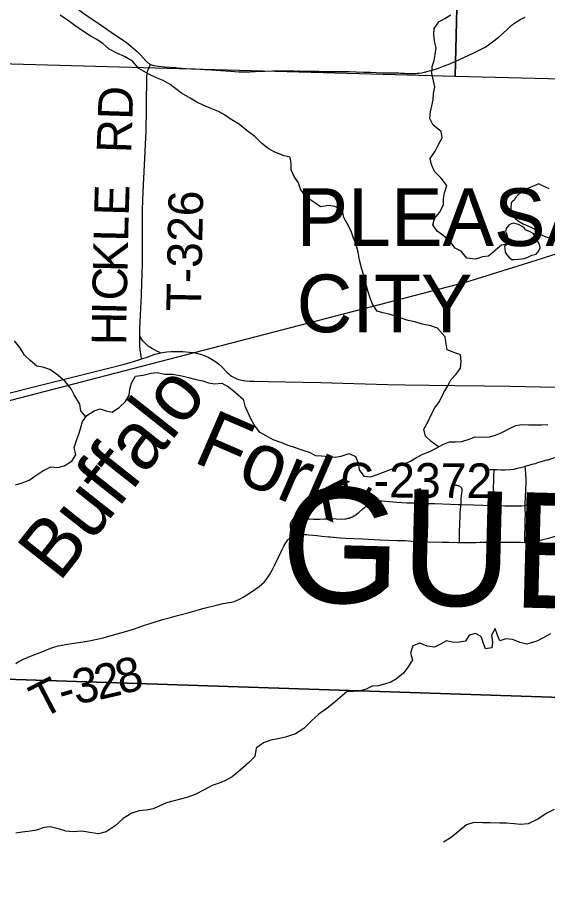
# Model space of a CAD drawing. Extents: x 0 to 34, y 0 to 22.
# Drawn here: x 5.129 to 5.999, y 19.787 to 21.203 of the extents above; entities that cross this region are included whole.
import ezdxf

# ---------------------------------------------------------------- set-up
doc = ezdxf.new("R2010")
doc.units = 0
for name, color, linetype in [('GM_X_Corporation', 7, 'Continuous'), ('GM_X_Corporation_Text', 7, 'Continuous'), ('GM_X_County_Road_Text', 7, 'Continuous'), ('GM_X_County_Text', 7, 'Continuous'), ('GM_X_Minor_Lake', 7, 'Continuous'), ('GM_X_Minor_River', 7, 'Continuous'), ('GM_X_Minor_River_Text', 7, 'Continuous'), ('GM_X_Rail_Line', 7, 'Continuous'), ('GM_X_State_Route', 7, 'Continuous'), ('GM_X_Township_Road', 7, 'Continuous'), ('GM_X_Township_Road_Text', 7, 'Continuous')]:
    doc.layers.add(name, color=color, linetype=linetype)

msp = doc.modelspace()

# ---------------------------------------------------------------- linework, layer by layer
at = {"layer": 'GM_X_Corporation'}
for points in [[(4.7823, 18.128), (4.7905, 18.3604), (4.8074, 19.5455), (4.8169, 20.042), (4.8194, 20.1261), (5.11, 20.116), (6.0551, 20.0845), (6.4901, 20.0752), (6.7204, 20.0659), (7.3691, 20.0515), (7.3901, 20.051), (7.814, 20.0425), (8.4311, 20.028), (8.4311, 21.3734), (1.6311, 21.3734)], [(4.0508, 18.1454), (4.7823, 18.128), (4.7905, 18.3604), (4.8074, 19.5455), (4.8169, 20.042), (4.8194, 20.1261), (5.11, 20.116), (6.0551, 20.0845), (6.4901, 20.0752), (6.7204, 20.0659), (7.3691, 20.0515), (7.3901, 20.051), (7.814, 20.0425), (8.4311, 20.028), (8.4311, 21.3734), (2.7987, 21.3734)], [(8.4311, 14.5734), (8.4311, 20.028), (7.814, 20.0425), (7.3901, 20.051), (7.3691, 20.0515), (6.7204, 20.0659), (6.4901, 20.0752), (6.0551, 20.0845), (5.11, 20.116), (4.8194, 20.1261), (4.8169, 20.042), (4.8074, 19.5455), (4.7905, 18.3604), (4.7823, 18.128)], [(8.4311, 16.0029), (8.4311, 20.028), (7.814, 20.0425), (7.3901, 20.051), (7.3691, 20.0515), (6.7204, 20.0659), (6.4901, 20.0752), (6.0551, 20.0845), (5.11, 20.116), (4.8194, 20.1261), (4.8169, 20.042), (4.8074, 19.5455), (4.7905, 18.3604), (4.7823, 18.128)]]:
    msp.add_lwpolyline(points, dxfattribs=at)
for points in [[(5.8536, 21.3734), (4.8467, 21.3734), (4.8451, 21.1681), (4.8435, 21.134), (5.8473, 21.1062)], [(6.8607, 21.3734), (5.8536, 21.3734), (5.8473, 21.1062), (6.8544, 21.0806)]]:
    msp.add_lwpolyline(points, close=True, dxfattribs=at)
at = {"layer": 'GM_X_Minor_Lake'}
for points in [[(6.0013, 20.9209), (5.9945, 20.9242), (5.9895, 20.9265), (5.9846, 20.9291), (5.9767, 20.9259), (5.9661, 20.9213), (5.9676, 20.9213), (5.9605, 20.9171), (5.9533, 20.9132), (5.9507, 20.9113), (5.9459, 20.9059), (5.9447, 20.9029), (5.941, 20.8998), (5.9391, 20.8979), (5.9384, 20.8892), (5.9392, 20.885), (5.9393, 20.8824), (5.9408, 20.8778), (5.9465, 20.8718), (5.9522, 20.8673), (5.9591, 20.8636), (5.9667, 20.8603), (5.9712, 20.8581), (5.9807, 20.8529), (5.9891, 20.8457), (5.9959, 20.8424), (6.0031, 20.8406)], [(5.9858, 20.8294), (5.9808, 20.8381), (5.9797, 20.8419), (5.9751, 20.8479), (5.9694, 20.8508), (5.9629, 20.8538), (5.9606, 20.8568), (5.9572, 20.859), (5.9511, 20.8624), (5.9432, 20.8646), (5.939, 20.8634), (5.9353, 20.8611), (5.9308, 20.8557), (5.9304, 20.8527), (5.9301, 20.8512), (5.9309, 20.8489), (5.9324, 20.844), (5.9328, 20.8414), (5.9333, 20.8304)], [(5.9333, 20.8304), (5.928, 20.8269), (5.9288, 20.8224), (5.9296, 20.8171), (5.9319, 20.8129), (5.9361, 20.8081), (5.9403, 20.8051), (5.9441, 20.8051), (5.952, 20.8056), (5.9607, 20.8068), (5.9652, 20.8084), (5.9731, 20.8119), (5.9803, 20.8138), (5.9833, 20.8173), (5.9844, 20.8192), (5.9866, 20.8241), (5.9858, 20.8294)]]:
    msp.add_lwpolyline(points, dxfattribs=at)
at = {"layer": 'GM_X_Minor_River'}
for points in [[(5.82, 20.4972), (5.808, 20.5059), (5.7984, 20.5149), (5.7961, 20.5266), (5.8028, 20.5388), (5.808, 20.5498), (5.8139, 20.5612), (5.8218, 20.5719), (5.8288, 20.5864), (5.8351, 20.5975), (5.8403, 20.6074), (5.849, 20.6169), (5.8561, 20.6265), (5.8571, 20.6379), (5.8562, 20.6485), (5.8441, 20.6529), (5.8342, 20.6566), (5.8323, 20.6664), (5.831, 20.6781), (5.8181, 20.692), (5.8074, 20.6961), (5.7931, 20.6986), (5.7813, 20.7026), (5.7703, 20.7048), (5.7605, 20.7081), (5.751, 20.7114), (5.7392, 20.7154), (5.7286, 20.7172), (5.7192, 20.7201), (5.7115, 20.7314), (5.7076, 20.7416), (5.7041, 20.7533), (5.7002, 20.7677), (5.6975, 20.7786), (5.694, 20.7892), (5.6901, 20.8039), (5.6884, 20.8168), (5.6849, 20.8293), (5.6807, 20.8398), (5.6768, 20.8515), (5.6699, 20.864), (5.6649, 20.8738), (5.6625, 20.8851), (5.65, 20.8918), (5.6398, 20.8936), (5.6266, 20.8915), (5.6171, 20.8979), (5.6022, 20.908), (5.5938, 20.9204), (5.5903, 20.9306), (5.583, 20.9411), (5.5784, 20.952), (5.5783, 20.963), (5.5767, 20.9729), (5.5669, 20.9754), (5.5513, 20.9813), (5.5403, 20.9872), (5.5304, 20.9955), (5.5189, 21.0071), (5.506, 21.0161), (5.4935, 21.0265), (5.4782, 21.0362), (5.4687, 21.0426), (5.4589, 21.0481), (5.4456, 21.0537), (5.435, 21.0577), (5.4236, 21.0633), (5.4126, 21.07), (5.3985, 21.0782), (5.3795, 21.0924), (5.3685, 21.0991), (5.3571, 21.1035), (5.3449, 21.1091), (5.3282, 21.1188), (5.3179, 21.1308), (5.305, 21.1382), (5.2921, 21.1438), (5.2795, 21.1504), (5.2693, 21.1598), (5.2586, 21.1665), (5.2484, 21.1721), (5.2358, 21.1803), (5.2236, 21.1893), (5.213, 21.1967), (5.1993, 21.206)], [(5.9333, 20.8304), (5.9235, 20.8284), (5.9133, 20.8203), (5.9021, 20.8107), (5.8919, 20.8091), (5.8806, 20.8056), (5.8666, 20.8073), (5.857, 20.8186), (5.8475, 20.8238), (5.8387, 20.8351), (5.8273, 20.8448), (5.8178, 20.8515), (5.8109, 20.862), (5.8135, 20.8723), (5.8217, 20.8822), (5.828, 20.8948), (5.8283, 20.9047), (5.8297, 20.9145), (5.8334, 20.9263), (5.8242, 20.9383), (5.8132, 20.9492), (5.8085, 20.9609), (5.8062, 20.9707), (5.8144, 20.983), (5.8196, 20.9929), (5.8259, 21.0047), (5.8243, 21.0153), (5.8114, 21.0257), (5.806, 21.0363), (5.8066, 21.0473), (5.8088, 21.0575), (5.811, 21.067), (5.8117, 21.0776), (5.8142, 21.0883), (5.8115, 21.0981), (5.8091, 21.1106), (5.8098, 21.1216), (5.8131, 21.1315), (5.8145, 21.1413), (5.8159, 21.1523), (5.8136, 21.1637), (5.8123, 21.175), (5.813, 21.1845), (5.8205, 21.1952), (5.8302, 21.2006), (5.84, 21.2068)], [(5.2414, 20.5468), (5.233, 20.5566), (5.2317, 20.5676), (5.2225, 20.5826), (5.2175, 20.5924), (5.2076, 20.6048), (5.1954, 20.6153), (5.1821, 20.6246), (5.1707, 20.6283), (5.1609, 20.6301), (5.1502, 20.6391), (5.1407, 20.6481), (5.1334, 20.6605), (5.1242, 20.6714)], [(5.1259, 20.435), (5.1368, 20.4385), (5.1485, 20.4424), (5.1594, 20.4501), (5.1711, 20.4582), (5.1842, 20.4644), (5.1956, 20.4637), (5.2058, 20.4661), (5.2182, 20.4738), (5.2249, 20.4845), (5.2225, 20.4962), (5.2269, 20.5095), (5.2303, 20.5198), (5.2332, 20.5293), (5.2358, 20.5392), (5.2429, 20.5487), (5.2549, 20.5564), (5.2651, 20.5596), (5.2749, 20.5563), (5.2848, 20.5545), (5.2964, 20.5626), (5.3065, 20.5718), (5.3125, 20.5821), (5.3135, 20.5919), (5.3161, 20.6022), (5.3228, 20.6132), (5.3353, 20.6153), (5.3485, 20.6184), (5.3583, 20.6193), (5.3708, 20.6168), (5.3836, 20.6165), (5.3988, 20.6137), (5.4101, 20.6115), (5.4226, 20.6079), (5.4332, 20.6057), (5.4427, 20.6024), (5.4529, 20.601), (5.4647, 20.6019), (5.4757, 20.5959), (5.4871, 20.5866), (5.4993, 20.5757), (5.5024, 20.5648), (5.507, 20.5538), (5.5113, 20.544), (5.5186, 20.5316), (5.5258, 20.5218), (5.5365, 20.5162), (5.5482, 20.5096), (5.5623, 20.5044), (5.5729, 20.5), (5.585, 20.4963), (5.5972, 20.4919), (5.6078, 20.4886), (5.6184, 20.4834), (5.6282, 20.4824), (5.64, 20.4817), (5.6502, 20.4807), (5.6604, 20.4823), (5.6732, 20.4862), (5.6838, 20.4814), (5.6884, 20.4713), (5.6897, 20.4595), (5.6977, 20.449)], [(5.6977, 20.449), (5.7083, 20.448), (5.7185, 20.4515), (5.7343, 20.4577), (5.7513, 20.464), (5.7626, 20.469), (5.7739, 20.4737), (5.7836, 20.4798), (5.7942, 20.4853), (5.8055, 20.4895), (5.8175, 20.4957), (5.8273, 20.5015), (5.8378, 20.5054), (5.8477, 20.5055), (5.8582, 20.5064), (5.8703, 20.5099), (5.8801, 20.5138), (5.8922, 20.5132), (5.9039, 20.5137), (5.9137, 20.5165), (5.9239, 20.5207), (5.9356, 20.5269), (5.9468, 20.5323), (5.9567, 20.534), (5.9676, 20.5333), (5.9888, 20.5335), (5.9994, 20.534)], [(6.0039, 20.1904), (5.993, 20.1843), (5.9813, 20.1781), (5.9651, 20.1734), (5.9537, 20.1763), (5.9416, 20.1811), (5.9306, 20.1821), (5.9204, 20.1786), (5.9166, 20.1884), (5.9127, 20.1993), (5.9071, 20.1883), (5.9084, 20.1769), (5.9077, 20.1671), (5.8971, 20.1655), (5.8932, 20.1764), (5.8901, 20.1862), (5.8806, 20.1907), (5.8705, 20.1879), (5.8645, 20.1784), (5.8543, 20.1767), (5.8445, 20.1763), (5.8331, 20.1788), (5.8233, 20.1734), (5.8136, 20.1684), (5.8011, 20.1701), (5.7893, 20.1749), (5.778, 20.1706), (5.7739, 20.1588), (5.7771, 20.1479), (5.7704, 20.1361), (5.7625, 20.1258), (5.7513, 20.1165), (5.7415, 20.1108), (5.7313, 20.1076), (5.7211, 20.1052), (5.7109, 20.1047), (5.7011, 20.0997), (5.6891, 20.0963), (5.6804, 20.0958), (5.6704, 20.0955)], [(5.6704, 20.0955), (5.6508, 20.0791), (5.6368, 20.0678), (5.6235, 20.0583), (5.6118, 20.0473), (5.5993, 20.0348), (5.5856, 20.0261), (5.569, 20.0208), (5.5565, 20.0182), (5.5448, 20.0156), (5.5327, 20.0114), (5.5209, 20.0027), (5.5186, 19.9891), (5.508, 19.9785), (5.4948, 19.9667), (5.4815, 19.9558), (5.4686, 19.9482), (5.4584, 19.9444), (5.4486, 19.9414), (5.4353, 19.9342), (5.421, 19.9266), (5.4073, 19.9217), (5.3967, 19.9187), (5.3839, 19.9157), (5.374, 19.9131), (5.3627, 19.9081), (5.3517, 19.9032), (5.3407, 19.901), (5.329, 19.8995), (5.3169, 19.8961), (5.3025, 19.8874), (5.2893, 19.8749), (5.2749, 19.865), (5.262, 19.862), (5.2477, 19.8643), (5.2348, 19.8666), (5.2204, 19.8655), (5.2087, 19.8663), (5.1981, 19.8697), (5.183, 19.8735), (5.1732, 19.8724), (5.1603, 19.8678), (5.1505, 19.8663), (5.1369, 19.8648), (5.1263, 19.8633)], [(6.0097, 19.9017), (5.9968, 19.8952), (5.9828, 19.8861), (5.9673, 19.8782), (5.9544, 19.8775), (5.9442, 19.8782), (5.9317, 19.8794), (5.9208, 19.8794), (5.9045, 19.8802), (5.892, 19.8802), (5.8777, 19.8806), (5.8659, 19.8768), (5.8531, 19.8666), (5.8406, 19.856), (5.8281, 19.8481)]]:
    msp.add_lwpolyline(points, dxfattribs=at)
at = {"layer": 'GM_X_Rail_Line'}
msp.add_lwpolyline([(6.5148, 20.9732), (5.9587, 20.7967), (5.8659, 20.7679), (5.0311, 20.5511), (4.5849, 20.4354), (4.3494, 20.3746), (4.3114, 20.365), (4.2729, 20.3524), (4.2311, 20.3354), (4.2068, 20.3213), (4.1788, 20.304), (4.0429, 20.1945)], dxfattribs=at)
at = {"layer": 'GM_X_State_Route'}
msp.add_lwpolyline([(5.1172, 20.5861), (5.1539, 20.5955), (5.1998, 20.6068), (5.2239, 20.6128), (5.248, 20.619), (5.2721, 20.6251), (5.3004, 20.6322), (5.3177, 20.637), (5.3314, 20.6413), (5.3328, 20.6417), (5.3402, 20.6442), (5.3549, 20.6493), (5.3637, 20.6517), (5.3707, 20.653), (5.3745, 20.6534), (5.3813, 20.6539), (5.3901, 20.654), (5.4007, 20.6537), (5.4108, 20.6531), (5.4187, 20.6522), (5.4249, 20.6509), (5.4297, 20.6495), (5.4356, 20.6474), (5.4431, 20.644), (5.4486, 20.641), (5.4539, 20.6376), (5.4589, 20.6338), (5.4639, 20.6291), (5.4725, 20.6201), (5.4766, 20.6165), (5.4806, 20.6136), (5.4847, 20.6111), (5.4892, 20.609), (5.492, 20.608), (5.4973, 20.6066), (5.504, 20.6057), (5.5101, 20.6053), (5.5176, 20.605), (5.5406, 20.6046), (5.5691, 20.6041), (5.6269, 20.6032), (5.663, 20.6021), (5.7362, 20.6), (5.7648, 20.5994), (5.804, 20.5988), (5.8468, 20.598), (5.8953, 20.5974), (5.9375, 20.597), (6.0121, 20.5956)], dxfattribs=at)
at = {"layer": 'GM_X_Township_Road'}
for points in [[(5.1288, 21.2967), (5.1376, 21.2889), (5.1458, 21.2822), (5.1599, 21.271), (5.1798, 21.2551), (5.1932, 21.244), (5.2053, 21.2343), (5.2254, 21.2187), (5.2315, 21.214), (5.2382, 21.209), (5.2534, 21.1983), (5.2632, 21.1917), (5.2899, 21.1735), (5.3043, 21.1639), (5.3081, 21.1611), (5.3113, 21.1587), (5.318, 21.1532), (5.3254, 21.1465), (5.3317, 21.1404), (5.3404, 21.1308), (5.3428, 21.1284), (5.3445, 21.1271), (5.3461, 21.126), (5.3475, 21.1253)], [(5.3475, 21.1253), (5.3491, 21.1246), (5.3511, 21.124), (5.3532, 21.1235), (5.3605, 21.1223), (5.3698, 21.1213), (5.3884, 21.12), (5.3921, 21.1198), (5.4057, 21.1188), (5.4206, 21.1179), (5.4367, 21.117), (5.4478, 21.1163), (5.4707, 21.1146), (5.4793, 21.114), (5.4855, 21.1135), (5.4923, 21.113), (5.4948, 21.1129), (5.4997, 21.1129), (5.5102, 21.1133), (5.5194, 21.1138), (5.535, 21.1144), (5.548, 21.1147), (5.5653, 21.1146), (5.5745, 21.1146), (5.583, 21.1145), (5.5867, 21.1144), (5.5891, 21.1145), (5.5922, 21.1145), (5.5952, 21.1144), (5.5982, 21.1144), (5.6019, 21.1143), (5.6049, 21.1143), (5.608, 21.1142), (5.611, 21.1142), (5.6147, 21.1141), (5.6214, 21.1142), (5.6239, 21.1141), (5.63, 21.1139), (5.6418, 21.1139), (5.6641, 21.1138), (5.674, 21.1136), (5.6851, 21.1132), (5.6969, 21.1125), (5.7043, 21.1123), (5.7085, 21.1123), (5.7177, 21.1119), (5.7294, 21.1115), (5.7355, 21.1114), (5.7411, 21.1116), (5.7448, 21.1114), (5.7478, 21.1115), (5.7515, 21.1112), (5.7546, 21.1112), (5.7576, 21.1109), (5.7613, 21.1109), (5.7644, 21.1107), (5.7675, 21.1106), (5.7712, 21.1104), (5.7773, 21.1103), (5.7825, 21.1106), (5.785, 21.1107), (5.7877, 21.111), (5.7918, 21.1117), (5.7968, 21.1128), (5.8089, 21.1158), (5.8148, 21.1175), (5.8201, 21.1194), (5.8282, 21.1225), (5.8385, 21.1265), (5.8544, 21.1332), (5.8767, 21.1437), (5.8901, 21.1501), (5.8955, 21.1531), (5.8997, 21.1557), (5.9107, 21.1638), (5.9205, 21.1716), (5.9266, 21.1769), (5.932, 21.1819), (5.9364, 21.1863), (5.9416, 21.1907), (5.9446, 21.1929), (5.9496, 21.1965), (5.9523, 21.1981), (5.955, 21.1996), (5.9589, 21.2015), (5.9623, 21.2029)], [(5.3299, 20.6789), (5.3299, 20.6896), (5.3303, 20.7045), (5.3309, 20.7132), (5.3314, 20.7257), (5.3326, 20.7455), (5.3333, 20.7678), (5.3339, 20.7803), (5.3341, 20.7989), (5.3343, 20.8474), (5.3344, 20.8617), (5.3345, 20.8872), (5.3352, 20.9158), (5.3364, 20.9387), (5.3382, 20.971), (5.3398, 21.0051), (5.3402, 21.0163), (5.3406, 21.0281), (5.3407, 21.0399), (5.3409, 21.0573), (5.3412, 21.0728), (5.3413, 21.0903), (5.3416, 21.104), (5.3421, 21.1103), (5.3427, 21.114), (5.3434, 21.1165), (5.3446, 21.1194), (5.3457, 21.1217), (5.3475, 21.1253)], [(5.3328, 20.6417), (5.332, 20.6473), (5.3308, 20.656), (5.3302, 20.6641), (5.3298, 20.6747), (5.3299, 20.6789)], [(5.3637, 20.6517), (5.3581, 20.6546), (5.3543, 20.6566), (5.3517, 20.6579), (5.3495, 20.6591), (5.3474, 20.6604), (5.3454, 20.6617), (5.3433, 20.6632), (5.3413, 20.6648), (5.3381, 20.6679), (5.3357, 20.6708), (5.3334, 20.6738), (5.3299, 20.6789)], [(5.9622, 20.4654), (5.9702, 20.4678), (5.9736, 20.4689), (5.9759, 20.4696), (5.9789, 20.4703), (5.9848, 20.472), (5.9982, 20.4759), (6, 20.4763), (6.0075, 20.4788), (6.0202, 20.4825)], [(5.9117, 20.4603), (5.9129, 20.4602), (5.9158, 20.4603), (5.923, 20.4599), (5.9286, 20.4598), (5.9372, 20.4603), (5.9434, 20.461), (5.9494, 20.4623), (5.9614, 20.4652), (5.9622, 20.4654)], [(5.9624, 20.4015), (5.9624, 20.4062), (5.9626, 20.4143), (5.9628, 20.418), (5.9632, 20.4242), (5.9635, 20.4303), (5.9638, 20.4365), (5.9638, 20.4419), (5.9636, 20.4443), (5.9636, 20.4467), (5.9634, 20.4501), (5.9633, 20.4521), (5.9625, 20.4612), (5.9622, 20.4654)], [(5.9034, 20.4601), (5.9046, 20.4602), (5.9064, 20.4602), (5.9117, 20.4603)], [(5.9094, 20.401), (5.9095, 20.4053), (5.9097, 20.4172), (5.9103, 20.4302), (5.9105, 20.442), (5.9108, 20.452), (5.9113, 20.4563), (5.9117, 20.4603)], [(5.9624, 20.4015), (5.9686, 20.4028), (5.9836, 20.4069), (6.0069, 20.4136), (6.0282, 20.42), (6.0449, 20.4247), (6.0611, 20.4291), (6.0767, 20.4334), (6.0827, 20.4352)], [(5.8441, 20.4345), (5.8462, 20.4345), (5.8484, 20.4344), (5.8496, 20.4343), (5.8509, 20.4341), (5.8522, 20.4338), (5.8534, 20.4334), (5.8542, 20.433), (5.855, 20.4326), (5.8557, 20.4319), (5.8564, 20.4313), (5.8571, 20.4304), (5.8575, 20.4298), (5.8578, 20.4291), (5.858, 20.4285)], [(5.858, 20.4285), (5.8581, 20.4276), (5.8582, 20.4267), (5.8582, 20.426), (5.8581, 20.4251), (5.858, 20.4241), (5.8578, 20.4219), (5.8571, 20.416), (5.8568, 20.4137), (5.8567, 20.4113), (5.8568, 20.4026)], [(5.7036, 20.4019), (5.706, 20.4034), (5.7072, 20.4041), (5.7085, 20.4047), (5.7098, 20.4054), (5.711, 20.4061), (5.7125, 20.4067), (5.7141, 20.4074), (5.7156, 20.4078), (5.7169, 20.4081), (5.719, 20.4083), (5.7205, 20.4085), (5.7228, 20.4086), (5.7245, 20.4086), (5.7275, 20.4086), (5.7335, 20.4083), (5.7515, 20.4068), (5.7682, 20.4056), (5.7788, 20.4052), (5.7886, 20.4048), (5.801, 20.4044), (5.803, 20.4044)], [(5.5777, 20.3724), (5.5781, 20.3736), (5.5789, 20.3752), (5.5797, 20.3764), (5.5804, 20.3776), (5.5812, 20.3784), (5.5819, 20.379), (5.5827, 20.3795), (5.584, 20.3798), (5.5867, 20.3799), (5.5886, 20.3799), (5.5966, 20.3796), (5.599, 20.3796), (5.6021, 20.3794), (5.6045, 20.3793), (5.6082, 20.3791), (5.6151, 20.3788), (5.6249, 20.3789), (5.6329, 20.3791), (5.636, 20.3794), (5.6415, 20.3795), (5.6521, 20.3791), (5.6595, 20.3789), (5.6663, 20.3792), (5.6684, 20.3794), (5.6701, 20.3796), (5.6719, 20.38), (5.6737, 20.3805), (5.6754, 20.3811), (5.6772, 20.3818), (5.6789, 20.3826), (5.6805, 20.3834), (5.6826, 20.3847), (5.6847, 20.3861), (5.6891, 20.3895), (5.6961, 20.3957), (5.7012, 20.4002), (5.7036, 20.4019)], [(5.8013, 20.3412), (5.8016, 20.3461), (5.8019, 20.3502), (5.8021, 20.3546), (5.8021, 20.3627), (5.8022, 20.3646), (5.8022, 20.3683), (5.8023, 20.3733), (5.8026, 20.3808), (5.8027, 20.3826), (5.8026, 20.3845), (5.8026, 20.3863), (5.8026, 20.3888), (5.8027, 20.3928), (5.8027, 20.3951), (5.803, 20.4044)], [(5.803, 20.4044), (5.814, 20.4041), (5.8521, 20.4028), (5.8568, 20.4026)], [(5.8544, 20.3403), (5.8545, 20.345), (5.8545, 20.3481), (5.8545, 20.3542), (5.8546, 20.3604), (5.8549, 20.3678), (5.8555, 20.3863), (5.8557, 20.3898), (5.8559, 20.3932), (5.8561, 20.3957), (5.8564, 20.3987), (5.8568, 20.4026)], [(5.8568, 20.4026), (5.8781, 20.4019), (5.9073, 20.4011), (5.9094, 20.401)], [(5.9094, 20.401), (5.919, 20.4008), (5.929, 20.4006), (5.9389, 20.4004), (5.9525, 20.4003), (5.9569, 20.4007), (5.9613, 20.4013), (5.9624, 20.4015)], [(5.9616, 20.3404), (5.9615, 20.3452), (5.9614, 20.352), (5.962, 20.3656), (5.9621, 20.3711), (5.9622, 20.3772), (5.9626, 20.3871), (5.9624, 20.3957), (5.9624, 20.4015)], [(5.9616, 20.3404), (5.9635, 20.3403), (5.9677, 20.3403), (5.9713, 20.3406), (5.9745, 20.3411), (5.9784, 20.3418), (5.9826, 20.3426), (5.985, 20.3432), (5.9878, 20.3439), (5.9912, 20.345), (6.0008, 20.3474), (6.0168, 20.3521), (6.0217, 20.3535), (6.0322, 20.3568), (6.044, 20.3605), (6.059, 20.3645), (6.0721, 20.368), (6.0805, 20.3704), (6.0852, 20.3719), (6.0993, 20.377), (6.104, 20.3787)], [(5.5775, 20.3483), (5.5775, 20.3543), (5.5775, 20.3567), (5.5775, 20.3604), (5.5772, 20.3665), (5.5773, 20.3695), (5.5774, 20.3709), (5.5777, 20.3724)], [(5.5775, 20.3483), (5.5787, 20.3489), (5.5812, 20.3501), (5.584, 20.351), (5.5855, 20.3515), (5.5875, 20.3519), (5.5896, 20.3523), (5.5922, 20.3527), (5.5938, 20.3529), (5.5947, 20.353), (5.5983, 20.3532), (5.6001, 20.3532), (5.6015, 20.3533), (5.6041, 20.3532), (5.6073, 20.353), (5.6202, 20.3518), (5.6287, 20.3509), (5.6394, 20.3498)], [(5.1264, 20.1416), (5.1304, 20.1444), (5.1347, 20.1468), (5.1402, 20.1495), (5.1535, 20.1547), (5.1622, 20.158), (5.168, 20.1602), (5.1749, 20.163), (5.1812, 20.1655), (5.1881, 20.1682), (5.1922, 20.1695), (5.196, 20.1704), (5.2, 20.1713), (5.2115, 20.1734), (5.2366, 20.1772), (5.247, 20.1788), (5.2574, 20.1809), (5.27, 20.184), (5.2866, 20.1885), (5.305, 20.1935), (5.3156, 20.1967), (5.3214, 20.1986), (5.336, 20.2038), (5.3501, 20.2085), (5.3673, 20.2137), (5.3823, 20.2177), (5.3919, 20.2202), (5.4111, 20.2254), (5.4332, 20.2318), (5.4578, 20.2381), (5.4638, 20.2395), (5.4729, 20.2411), (5.4803, 20.2425), (5.4846, 20.2437), (5.4887, 20.2452), (5.4933, 20.2473), (5.4994, 20.2506), (5.51, 20.2571), (5.5188, 20.263), (5.5258, 20.2682), (5.5302, 20.2718), (5.5338, 20.2753), (5.5366, 20.2787), (5.5403, 20.2838), (5.5427, 20.2874), (5.5471, 20.295), (5.5517, 20.3038), (5.5581, 20.3172), (5.563, 20.3278), (5.5664, 20.3344), (5.5694, 20.3398), (5.5718, 20.3433), (5.5727, 20.3445), (5.5733, 20.3451), (5.5738, 20.3457), (5.5747, 20.3465), (5.5753, 20.347), (5.5759, 20.3474), (5.5765, 20.3478), (5.5775, 20.3483)], [(5.6394, 20.3498), (5.6423, 20.3495), (5.6585, 20.348), (5.6678, 20.3476), (5.6951, 20.3461), (5.7236, 20.3449), (5.7528, 20.3438), (5.7652, 20.3434), (5.7812, 20.3422), (5.7917, 20.3416), (5.8013, 20.3412)], [(5.8013, 20.3412), (5.8259, 20.3408), (5.8377, 20.3406), (5.8519, 20.3403), (5.8544, 20.3403)], [(5.8544, 20.3403), (5.868, 20.3403), (5.8742, 20.3403), (5.8761, 20.3403), (5.881, 20.3405), (5.8882, 20.3409), (5.8907, 20.3409), (5.8931, 20.3408), (5.8949, 20.3408), (5.8974, 20.3408), (5.8992, 20.3408), (5.9084, 20.3408), (5.9189, 20.3408), (5.9282, 20.3408), (5.9313, 20.3408), (5.9338, 20.3407), (5.9387, 20.3407), (5.9456, 20.3406), (5.9511, 20.3406), (5.9542, 20.3406), (5.9616, 20.3404)]]:
    msp.add_lwpolyline(points, dxfattribs=at)

# ---------------------------------------------------------------- texts
at = {"layer": 'GM_X_Corporation_Text'}
for s, p in [('PLEASANT', (5.5872, 20.8271)), ('CITY', (5.5872, 20.6855))]:
    msp.add_text(s, height=0.0947, rotation=0, dxfattribs=at).set_placement(p)
at = {"layer": 'GM_X_County_Road_Text'}
msp.add_text('C-2372', height=0.05682, rotation=359.6397, dxfattribs=at).set_placement((5.6587, 20.4148))
at = {"layer": 'GM_X_County_Text'}
msp.add_text('GUERNSEY COUNTY', height=0.189394, rotation=358.543, dxfattribs=at).set_placement((5.5592, 20.2436))
at = {"layer": 'GM_X_Minor_River_Text'}
for s, rotation, p in [('Buffalo', 51.577, (5.1977, 20.2737)), ('Fork', 336.5812, (5.4151, 20.4736))]:
    msp.add_text(s, height=0.09469, rotation=rotation, dxfattribs=at).set_placement(p)
at = {"layer": 'GM_X_Township_Road_Text'}
for s, height, rotation, p in [('RD', 0.05682, 88.1088, (5.3159, 20.9791)), ('E', 0.0568, 88.3369, (5.3117, 20.8763)), ('T-326', 0.05682, 88.8743, (5.4302, 20.7192)), ('L', 0.0568, 88.7271, (5.3107, 20.8339)), ('K', 0.0568, 88.7395, (5.3096, 20.7839)), ('C', 0.0568, 88.7431, (5.3086, 20.7372)), ('I', 0.0568, 88.79, (5.3081, 20.7139)), ('H', 0.0568, 89.3625, (5.3076, 20.6641)), ('8', 0.0568, 15.1423, (5.2987, 20.09)), ('2', 0.0568, 13.0062, (5.2624, 20.0815)), ('3', 0.0568, 10.2092, (5.225, 20.0747)), ('T', 0.0568, 27.5751, (5.1692, 20.0499)), ('-', 0.0568, 16.3598, (5.2041, 20.0685))]:
    msp.add_text(s, height=height, rotation=rotation, dxfattribs=at).set_placement(p)

doc.saveas('drawing.dxf')
